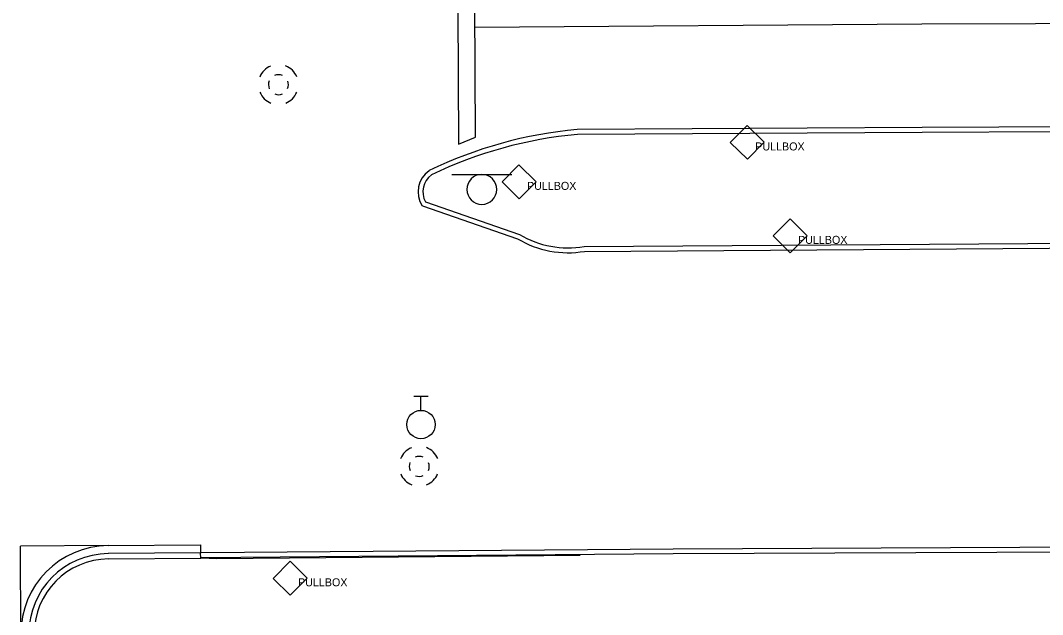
# Model space of a CAD drawing. Extents: x 2145380 to 2157287, y 139568 to 149130.
# Drawn here: x 2150890.7 to 2151018.5, y 148231.8 to 148306.1 of the extents above; entities that cross this region are included whole.
import ezdxf

# ---------------------------------------------------------------- set-up
doc = ezdxf.new("R2010")
doc.units = 0
for name, color, linetype in [('Default', 7, 'Continuous'), ('PR_PREVIOUSLY CONSTRUCTED', 7, 'Continuous'), ('TOPO_Curb Back', 7, 'Continuous'), ('TOPO_DRAIN_Manhole', 7, 'Continuous'), ('TOPO_Misc Line', 7, 'Continuous'), ('TOPO_Power Pullbox', 7, 'Continuous'), ('TOPO_Sign', 7, 'Continuous'), ('TOPO_Water Valve', 7, 'Continuous')]:
    doc.layers.add(name, color=color, linetype=linetype)

# ---------------------------------------------------------------- blocks, each defined once
blk = doc.blocks.new('MHEXST')
at = {"layer": 'TOPO_DRAIN_Manhole'}
for centre, radius, start, end in [((-0.14, 0.26), 12.7, 112.97475, 158.26364), ((-0.14, 0.26), 12.7, 22.07441, 68.69913), ((-0.08, 0.11), 6.35, 157.97219, 204.16105), ((-0.08, 0.11), 6.35, 66.19406, 113.69103), ((-0.08, 0.11), 6.35, 336.80229, 21.40458), ((-0.14, 0.26), 12.7, 202.6921, 248.19382), ((-0.08, 0.11), 6.35, 248.57914, 293.19947), ((-0.14, 0.26), 12.7, 291.79631, 337.30323)]:
    blk.add_arc(centre, radius, start, end, dxfattribs=at)
blk = doc.blocks.new('pulbox')
at = {"layer": 'Default'}
blk.add_lwpolyline([(-5.38, -0.01), (-0.02, 5.42), (5.4, 0.06), (0.05, -5.36), (-5.38, -0.01)], dxfattribs=at)
blk.add_text('PULLBOX', height=2.54, dxfattribs=at).set_placement((2.54, -2.54))
blk = doc.blocks.new('WATVAL')
at = {"layer": 'Default'}
for p, q in [((-2.25, 9), (2.25, 9)), ((0, 4.5), (0, 9))]:
    blk.add_line(p, q, dxfattribs=at)
blk.add_circle((0, 0), 4.5, dxfattribs=at)

msp = doc.modelspace()

# ---------------------------------------------------------------- linework, layer by layer
at = {"layer": 'PR_PREVIOUSLY CONSTRUCTED'}
for p, q in [((2150901.73, 148240.4), (2150913.26, 148240.49)), ((2150913.26, 148240.49), (2150913.27, 148239.49)), ((2150913.27, 148239.49), (2150901.74, 148239.4))]:
    msp.add_line(p, q, dxfattribs=at)
for points in [[(2150901.73, 148240.4), (2150890.75, 148240.31)], [(2150890.81, 148229.33), (2150890.75, 148240.31)], [(2150901.74, 148238.73), (2150913.28, 148238.82), (2150913.27, 148239.49)]]:
    msp.add_lwpolyline(points, dxfattribs=at)
for radius in [11, 10, 9.33]:
    msp.add_arc((2150901.81, 148229.4), radius, 90.4468, 180.3443, dxfattribs=at)
at = {"layer": 'TOPO_Curb Back'}
for points in [[(2151070.47, 148292.99), (2151003.44, 148292.66), (2150960.33, 148292.42)], [(2151070.29, 148292.39), (2151003.44, 148292.06), (2150960.36, 148291.82)], [(2150940.98, 148282.88), (2150952.88, 148278.76)], [(2150941.38, 148283.38), (2150953.14, 148279.31)], [(2150961.21, 148277.79), (2151065.99, 148278.51)], [(2150961.26, 148277.19), (2151065.8, 148277.91)], [(2151053.97, 148239.7), (2151032.98, 148239.63), (2150972.34, 148239.35), (2150913.36, 148238.89), (2150913.3, 148238.87)], [(2150960.71, 148239.16), (2150915.3, 148238.76), (2150913.33, 148238.82)], [(2151054.16, 148240.3), (2151032.98, 148240.23), (2150972.34, 148239.95), (2150913.38, 148239.49)]]:
    msp.add_lwpolyline(points, dxfattribs=at)
for centre, radius, start, end in [((2150965.23, 148238.89), 53.76, 95.2286, 115.8064), ((2150965.23, 148238.89), 53.15, 95.2554, 115.7524), ((2150943.67, 148284.64), 3.22, 124.9486, 213.1843), ((2150943.67, 148284.64), 2.62, 125.9505, 208.9026), ((2150959.21, 148289.43), 12.41, 239.3103, 279.4942), ((2150959.21, 148289.43), 11.81, 239.0196, 279.7226)]:
    msp.add_arc(centre, radius, start, end, dxfattribs=at)
at = {"layer": 'TOPO_Misc Line'}
msp.add_lwpolyline([(2150945.29, 148332.86), (2150945.51, 148290.58), (2150947.63, 148291.45), (2150947.4, 148332.87)], close=True, dxfattribs=at)
msp.add_lwpolyline([(2151074.44, 148305.81), (2151003.42, 148305.59), (2150947.55, 148305.2)], dxfattribs=at)
at = {"layer": 'TOPO_Sign'}
for points in [[(2150944.66, 148286.81), (2150952.16, 148286.81)], [(2150948.41, 148286.8), (2150948.41, 148286.8)], [(2150946.55, 148284.94), (2150946.55, 148284.94)], [(2150950.28, 148284.94), (2150950.28, 148284.94)], [(2150948.41, 148283.07), (2150948.41, 148283.07)]]:
    msp.add_lwpolyline(points, dxfattribs=at)
for start, end in [(90, 180), (360, 90), (180, 270), (270, 0)]:
    msp.add_arc((2150948.41, 148284.94), 1.87, start, end, dxfattribs=at)

# ---------------------------------------------------------------- block references
at = {"layer": 'TOPO_DRAIN_Manhole', "xscale": 0.19685000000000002, "yscale": 0.19685000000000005}
for p in [(2150923.01, 148298.01), (2150940.61, 148250.28)]:
    msp.add_blockref('MHEXST', p, dxfattribs=at)
at = {"layer": 'TOPO_Power Pullbox', "xscale": 0.39370000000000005, "yscale": 0.3937000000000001}
for p in [(2150981.59, 148290.81), (2150953.06, 148285.88), (2150986.94, 148279.13), (2150924.45, 148236.31)]:
    msp.add_blockref('pulbox', p, dxfattribs=at)
at = {"layer": 'TOPO_Water Valve', "xscale": 0.39370000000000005, "yscale": 0.3937000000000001}
msp.add_blockref('WATVAL', (2150940.81, 148255.54), dxfattribs=at)

doc.saveas('drawing.dxf')
